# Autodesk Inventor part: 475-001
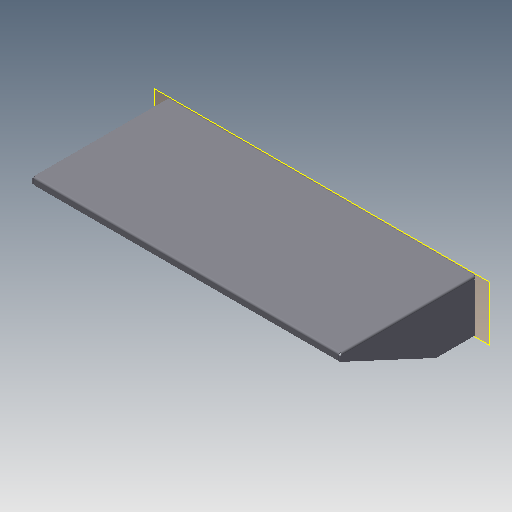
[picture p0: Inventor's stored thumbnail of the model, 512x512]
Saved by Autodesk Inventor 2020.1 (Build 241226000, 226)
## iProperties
Created: 2010-09
Part Number: 475-001
Material: Stal
Document SubType Name: Konstrukcje blachowe
Density: 7.85 g/cm^3
Sheet Metal Rule: Blacha stalowa 2.5 mm/Okrągły
Sheet Metal Width: 1191,310 mm
Sheet Metal Length: 561,310 mm
Sheet Metal Area: 668693,749 mm^2
Description: Podajnik
Flat Pattern Width: 119.131 cm
Flat Pattern Length: 56.131 cm
Flat Pattern Area: 6686.94 cm^2
Appearance: Metal-Stal
Mass: 11622.4 g
Surface Area: 11937.2 cm^2
Volume: 1480.56 cm^3
Designer: F.Stasiak
Manager: www.cadconsulting.pl
Company: Fabian Stasiak CAD Consulting
Author: F.Stasiak
Subject: Zbiór ćwiczeń. Autodesk Inventor 2020. Kurs podstawowy
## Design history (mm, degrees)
sketch "Szkic9"
  geometry: L1 (-407.888, 145.936)-(492.112, 145.936); L2 (492.112, 145.936)-(492.112, -4.064); L3 (492.112, -4.064)-(-407.888, -4.064); L4 (-407.888, -4.064)-(-407.888, 145.936); 1 further point
  constraints: 8 end point, 2 parallel, 1 horizontal, 1 perpendicular
  dimensions: "d101" = 150 distance of L1.end L2.end
extrude "Wyciągnięcie proste1" new body sketch "Szkic9" distance "d102" = 400; taper "d103" = 0 deg
chamfer "Faza1" distance "d104" = 280; stored, may be unused: second distance "d105" = 130, angle "d106" = 45 deg
feature "Skorupa1" dims "d108" = 2.5 (= Grubość)
feature "Narożnik6" dims "d114" = 10 (= RozmiarPodcięciaNarożnika), "d115" = 2.5 (= PromieńGięcia), "d116" = 2.5 (= Wielk_odstępu), "d117" = 0, "d118" = 10, "d163" = 2.5 (= Grubość)
feature "Gięcie11" dims "d119" = 2.5 (= SzerokośćGięciaPodcięcia), "d120" = 1.25 (= GłębokośćGięciaPodcięcia), "d121" = 5 (= MinimalnaPozostałość), "d122" = 2.5 (= PromieńGięcia), "d123" = 2.5 (= PromieńGięcia), "d163" = 2.5 (= Grubość), "OdstępPołączenia" = 0.01
feature "Gięcie12" dims "d124" = 2.5 (= SzerokośćGięciaPodcięcia), "d125" = 1.25 (= GłębokośćGięciaPodcięcia), "d126" = 5 (= MinimalnaPozostałość), "d127" = 2.5 (= PromieńGięcia), "d128" = 2.5 (= PromieńGięcia), "d163" = 2.5 (= Grubość), "OdstępPołączenia" = 0.01
feature "Gięcie13" dims "d129" = 2.5 (= SzerokośćGięciaPodcięcia), "d130" = 1.25 (= GłębokośćGięciaPodcięcia), "d131" = 5 (= MinimalnaPozostałość), "d132" = 2.5 (= PromieńGięcia), "d133" = 2.5 (= PromieńGięcia), "d163" = 2.5 (= Grubość), "OdstępPołączenia" = 0.01
node "Kołnierz3"
node "Płaszczyzna konstrukcyjna4"
node "Powierzchnia4"
  sketch "Szkic11"
    geometry: L1 (887.773, 0)-(857.5, 0); L2 (857.5, 0)-(857.5, 140); L3 (857.5, 140)-(887.773, 140); L4 (887.773, 140)-(887.773, 0); L5 (892.5, 0)-(895, 0) reference; L6 (892.5, 130)-(892.5, 0) reference; 1 further point
    constraints: 8 end point, 2 parallel, 1 collinear, 1 horizontal, 1 perpendicular
    dimensions: "d146" = 140 distance of L3.end L1.start; "d147" = 35 distance between parallel lines of L6 L2
node "Płaszczyzna konstrukcyjna5"
mirror "Odbicie lustrzane3"
sketch "Szkic12"
  geometry: L1 (890, 0)-(857.5, 0) reference; L2 (892.5, 140)-(892.5, 0) reference; L3 (872.5, 115)-(872.5, 45); 1 further point
  constraints: 2 end point, 1 parallel
  dimensions: "d153" = 45 distance from line of L1 L3.end; "d154" = 115 distance from line of L3.start L1; "d155" = 20 distance from line of L2 L3.end
hole "Hole2" sketch "Szkic12" at (872.5, 115), (872.5, 45) diameter "d156" = 9; stored, may be unused: countersink angle "d160" = 90 deg, drill point angle "d162" = 118 deg; dims "d157" = 6, "d158" = 17.3, "d159" = 6.3, "d161" = 2.5 (= Grubość)
mirror "Odbicie lustrzane4"
node "Bryła4"
sketch "Szkic10"
  geometry: L1 through (0, 0) direction (0, -1); L2 (0, -20)-(890, -20); L3 (890, -20)-(890, 0); 1 other entity
  constraints: 5 end point, 2 vertical, 2 other
feature "Płyta8" dims "d134" = 2.5 (= SzerokośćGięciaPodcięcia), "d135" = 1.25 (= GłębokośćGięciaPodcięcia), "d136" = 5 (= MinimalnaPozostałość), "d137" = 2.5 (= PromieńGięcia), "d138" = 20, "d139" = 90 deg, "d140" = 2.5 (= PromieńGięcia), "d141" = 10 (= RozmiarPodcięciaNarożnika), "d142" = 2.5 (= Wielk_odstępu), "d143" = 2.5 (= Rozmiar_promienia_Jacobiego), "d163" = 2.5 (= Grubość), "OdstępPołączenia" = 0.01
feature "Gięcie14" dims "d134" = 2.5 (= SzerokośćGięciaPodcięcia), "d135" = 1.25 (= GłębokośćGięciaPodcięcia), "d136" = 5 (= MinimalnaPozostałość), "d137" = 2.5 (= PromieńGięcia), "d138" = 20, "d139" = 90 deg, "d140" = 2.5 (= PromieńGięcia), "d163" = 2.5 (= Grubość), "OdstępPołączenia" = 0.01
feature "Narożnik5" dims "d138" = 20, "d139" = 90 deg, "d141" = 10 (= RozmiarPodcięciaNarożnika), "d142" = 2.5 (= Wielk_odstępu), "d143" = 2.5 (= Rozmiar_promienia_Jacobiego)
feature "Płyta9" dims "d148" = 2.5 (= PromieńGięcia), "d149" = 2.5 (= SzerokośćGięciaPodcięcia), "d151" = 5 (= MinimalnaPozostałość), "d163" = 2.5 (= Grubość)
feature "Gięcie15" dims "d148" = 2.5 (= PromieńGięcia), "d149" = 2.5 (= SzerokośćGięciaPodcięcia), "d150" = 1.25 (= GłębokośćGięciaPodcięcia), "d151" = 5 (= MinimalnaPozostałość), "d152" = 2.5 (= PromieńGięcia), "d163" = 2.5 (= Grubość), "OdstępPołączenia" = 0.01
feature "Definicja1"
other parameters: "Grubość" = 2.5 (derived), "WspółczynnikK" = 4.4, "PromieńGięcia" = 2.5 (= Grubość), "SzerokośćGięciaPodcięcia" = 2.5 (= Grubość), "GłębokośćGięciaPodcięcia" = 1.25 (= 0.5 x Grubość), "MinimalnaPozostałość" = 5 (= 2 x Grubość), "PromieńPrzejścia" = 2.5 (= PromieńGięcia), "Rozmiar_promienia_Jacobiego" = 2.5 (= PromieńGięcia), "Wielk_odstępu" = 2.5 (= Grubość), "d2" = 2.5 (= PromieńGięcia), "d144" = 0.1, "Grubość" = 2.5, "GłębokośćGięciaPodcięcia" = 1.25, "MinimalnaPozostałość" = 5, "PromieńGięcia" = 2.5, "PromieńPrzejścia" = 2.5, "Rozmiar_promienia_Jacobiego" = 2.5, "SzerokośćGięciaPodcięcia" = 2.5, "Wielk_odstępu" = 2.5
